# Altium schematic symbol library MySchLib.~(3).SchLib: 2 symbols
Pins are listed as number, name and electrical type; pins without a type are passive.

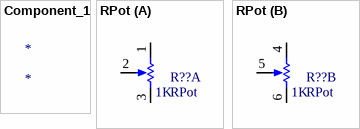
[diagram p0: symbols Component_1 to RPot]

## Component_1
designator *

## RPot
designator R??  value 1K
Potentiometer; Sim Note: Enter the Resistance value and the set point into parameter fields.; Set Position: 0.5
footprint VR5 (Thru-Hole; 3 Leads)
simulation model POT (Potentiometer)
part A pins: 1 TOP, 2 TAP, 3 BOT
part B pins: 4 TOP, 5 TAP, 6 BOT
1 alternate drawing of the same symbol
